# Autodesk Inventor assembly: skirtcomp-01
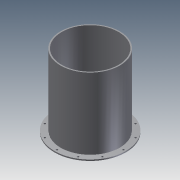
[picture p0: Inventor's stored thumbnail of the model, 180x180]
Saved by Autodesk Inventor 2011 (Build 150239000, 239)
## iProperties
Created: 2010-07
Part Number: skirtcomp-01
Document SubType Name: Assembly
Designer: mklassen
OD: 24.000 in
THK: 0.500 in
LEN: 3.000 ft
SVOFS: 6.000 in
SKLEN: 2.500 ft
SKFWDT: 3.000 in
SKFTHK: 0.500 in
Author: mklassen
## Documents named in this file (3)
- O:\cadd\tutorials\inventor 2011\iLogic\skirtcomp-01.iam
- O:\cadd\tutorials\inventor 2011\iLogic\SkirtFlange-02-01.ipt
- O:\cadd\tutorials\inventor 2011\iLogic\Skirt-02-01.ipt
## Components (2 placed, 2 different names)
1. SkirtFlange-02:1
2. Skirt-02:1
